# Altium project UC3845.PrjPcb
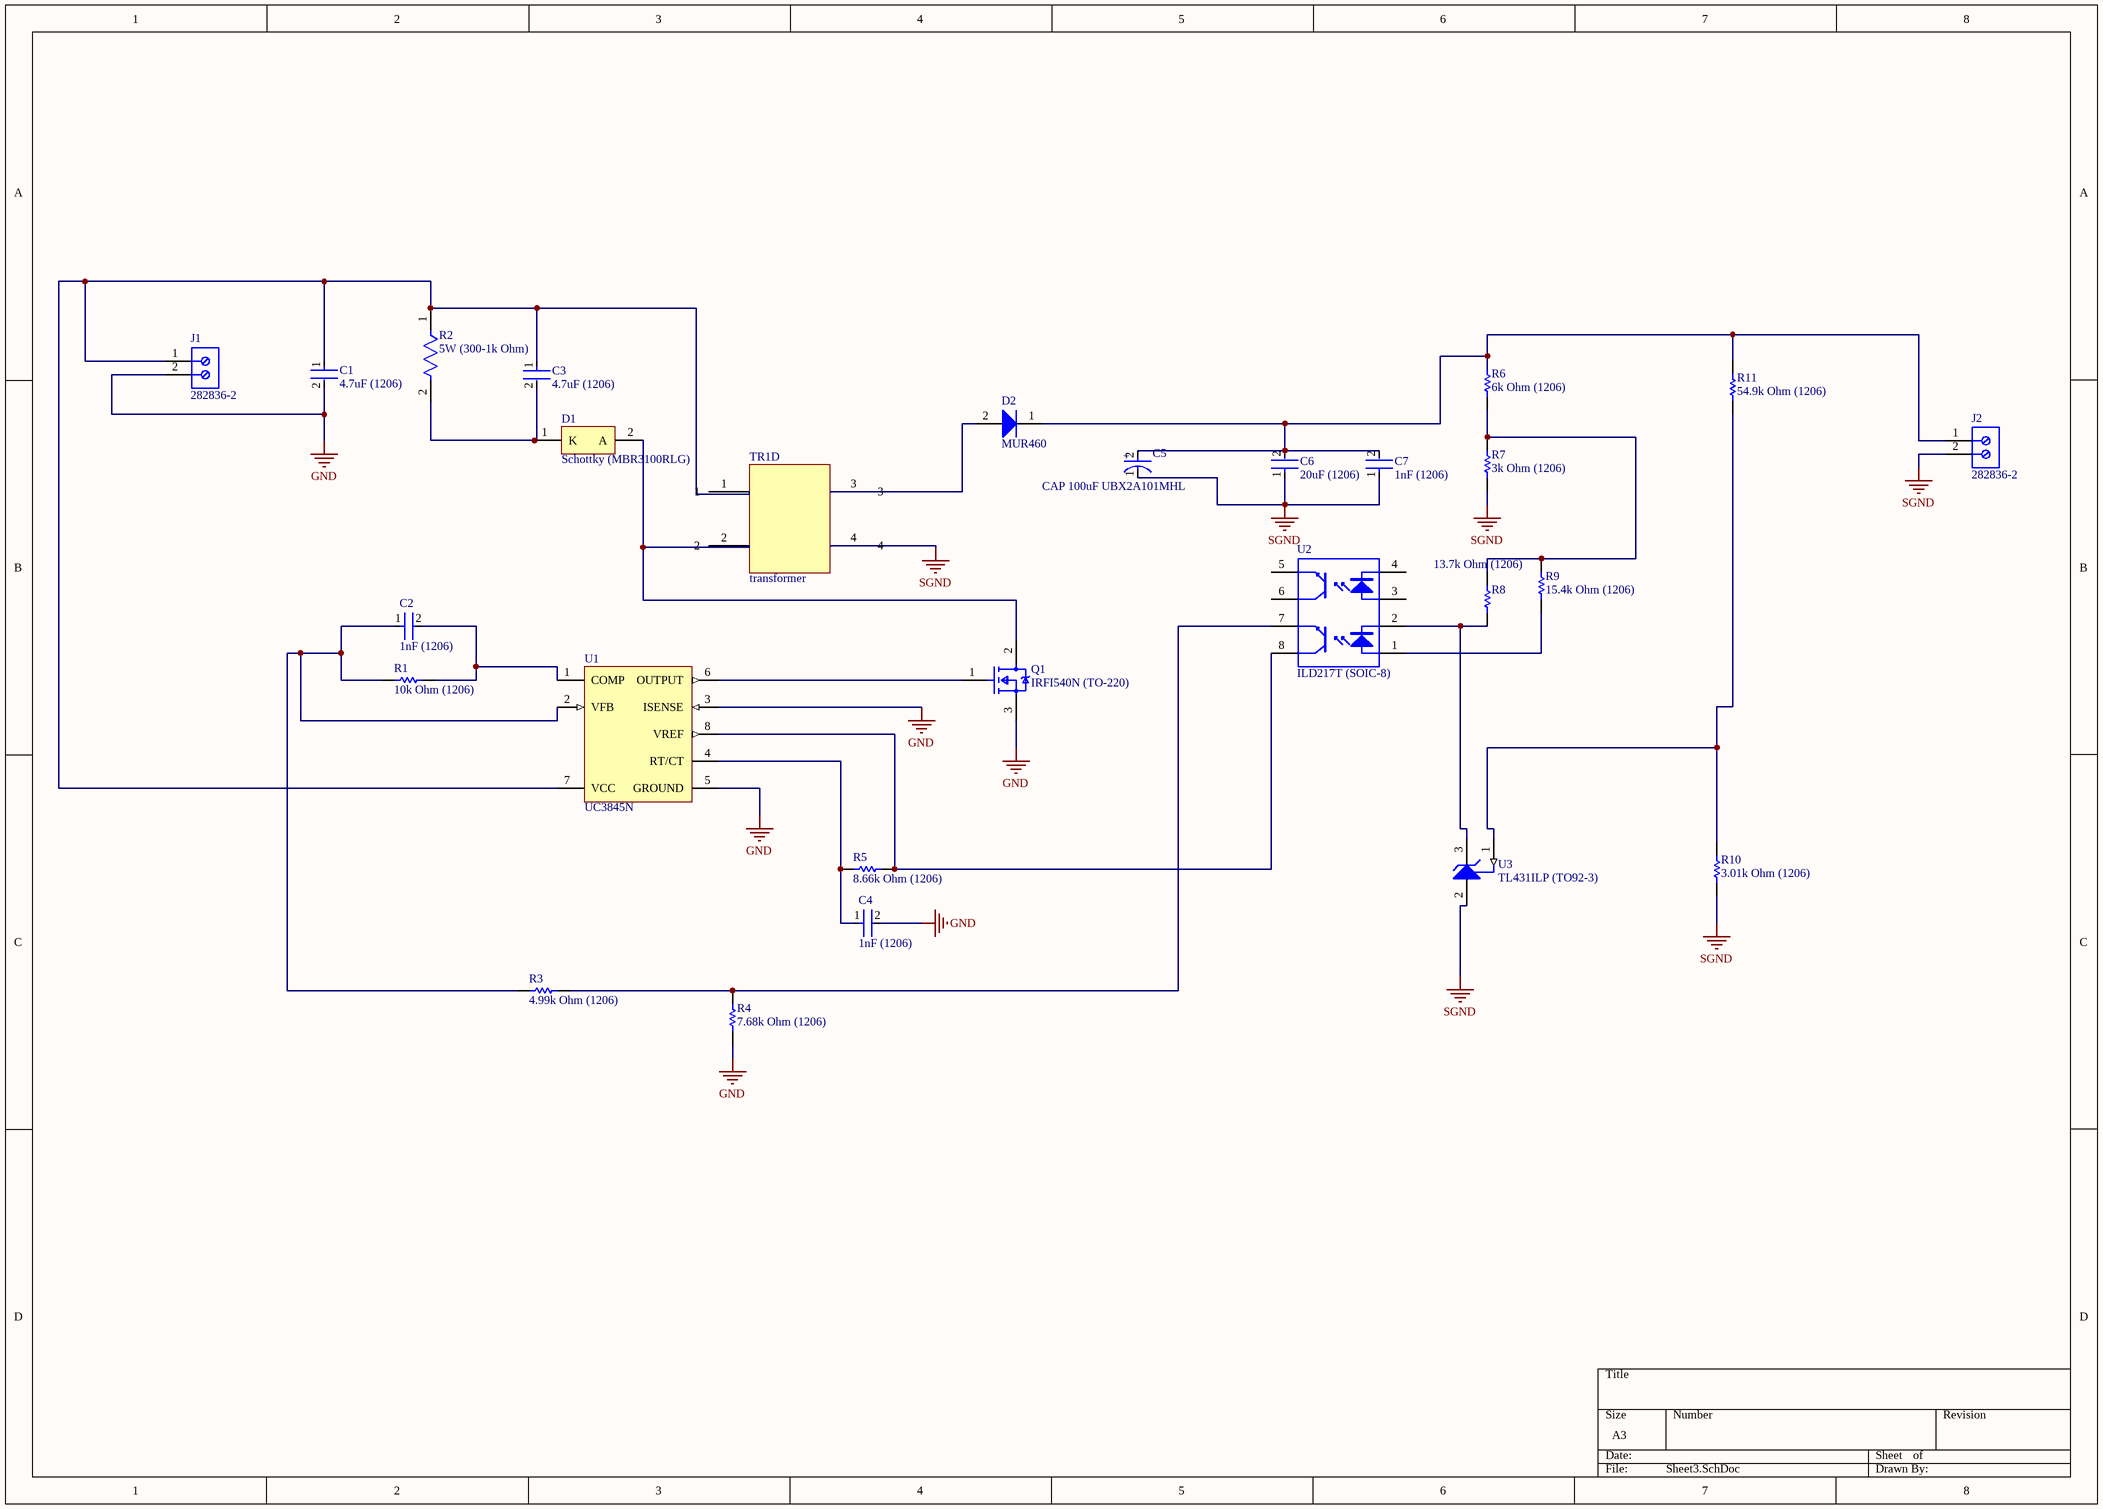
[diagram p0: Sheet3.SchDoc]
1 sheet, 27 parts. Net scope: global (net labels, ports and power ports of the same name join across sheets).
Board file: PCB2.PcbDoc

## Sheet Sheet3.SchDoc
size A3

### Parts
C1  4.7uF (1206)  [FP-C1206C-EB-MFG]
C2  1nF (1206)  [FP-C1206C-EB-MFG]
C3  4.7uF (1206)  [FP-C1206C-EB-MFG]
C4  1nF (1206)  [FP-C1206C-EB-MFG]
C5  CAP 100uF UBX2A101MHL  [FP-UBX2A101MHL-MFG]
C6  20uF (1206)  [FP-C1206C-EB-MFG]
C7  1nF (1206)  [FP-C1206C-EB-MFG]
D1  Schottky (MBR3100RLG)  [ONSC-AXIAL_LEAD-2-267-05_V]
D2  MUR460  [ONSC-AXIAL_LEAD-2-267-05_V]
J1  282836-2  [TECO-282836-2_V]
J2  282836-2  [TECO-282836-2_V]
Q1  IRFI540N (TO-220)  [FP-PG-TO220-3-MFG]
R1  10k Ohm (1206)  [RESC3216X60X45NL10T20]
R2  5W (300-1k Ohm)  [FP-SQP500-MFG]
R3  4.99k Ohm (1206)  [RESC3216X60X45NL10T20]
R4  7.68k Ohm (1206)  [RESC3216X60X45NL10T20]
R5  8.66k Ohm (1206)  [RESC3216X60X45NL10T20]
R6  6k Ohm (1206)  [RESC3216X60X45NL10T20]
R7  3k Ohm (1206)  [RESC3216X60X45NL10T20]
R8  13.7k Ohm (1206)  [RESC3216X60X45NL10T20]
R9  15.4k Ohm (1206)  [RESC3216X60X45NL10T20]
R10  3.01k Ohm (1206)  [RESC3216X60X45NL10T20]
R11  54.9k Ohm (1206)  [RESC3216X60X45NL10T20]
TR1  transformer  [Transformer_flyback]  (part D of 4)
U1  UC3845N  [P0008A]
U2  ILD217T (SOIC-8)  [VISH-SOIC-8_C_V]
U3  TL431ILP (TO92-3)  [LP0003A]

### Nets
GND: C1.2 C4.2 J1.2 Q1.3(S) R4.1 U1.3(ISENSE) U1.5(GROUND)
SGND: C5.1(C) C6.1 C7.1 J2.2 R7.2 R10.2 TR1.4 U3.2(ANODE)
NetC1_1: C1.1 C3.1 J1.1 R2.1 TR1.1 U1.7(VCC)
NetC2_1: C2.1 R1.2 R3.2 U1.2(VFB)
NetC2_2: C2.2 R1.1 U1.1(COMP)
NetC3_2: C3.2 D1.1(K) R2.2
NetC4_1: C4.1 R5.2 U1.4(RT/CT)
NetC5_2: C5.2(A) C6.2 C7.2 D2.1(K) J2.1 R6.1 R11.1
NetD1_2: D1.2(A) Q1.2(D) TR1.2
NetD2_2: D2.2(A) TR1.3
NetQ1_1: Q1.1(G) U1.6(OUTPUT)
NetR3_1: R3.1 R4.2 U2.7(E)
NetR5_1: R5.1 U1.8(VREF) U2.8(C)
NetR6_2: R6.2 R7.1 R8.1 R9.1
NetR8_2: R8.2 U2.2(K) U3.3(CATHODE)
NetR9_2: R9.2 U2.1(A)
NetR10_1: R10.1 R11.2 U3.1(REF)

Not connected (* = marked no-connect by the designer): U2 3(A) 4(K) 5(E) 6(C)

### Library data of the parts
C1-C4 C6 C7 = CMP-03020-000955-1: Multilayer Ceramic Capacitor, C Series, 1000 Pf, - 5%, C0g / Np0, 100 V, 1206 [3216 Metric] Rohs Compliant: Yes; Manufacturer: KEMET; Manufacturer Part Number: C1206C102J1GACTU; Capacitance: 1,000 pF; Voltage Rating: 100 V; Tolerance: 0.05; Automotive Grade: Grade 0; Temperature Coefficient: 15%; Value: 1,000 pF
C5 = CMP-12462-000004-1: CAP ALUM 100UF 20% 100V RADIAL; Manufacturer: Nichicon; Material: Aluminum; Automotive Grade: Grade 0; Ripple Current: 950mA; Leakage Current: 300uA; Life: 1000Hours; Dissipation Factor: 8%
D1 = CMP-1055-00020-1: Rectifier, 2-Pin Axial_Lead, Pb-Free, Tape and Reel; Manufacturer: On Semiconductor; Configuration: Single; IFSM Max (A): 150
D2 = CMP-0902-00067-1: SWITCHMODE(TM) Power Rectifier, 2-Pin Axial_Lead, Pb-Free, Bulk Bag; Manufacturer: On Semiconductor; IFSM Max (A): 110; Type: Ultrafast; VRRM Max (V): 600
J1 J2 = CMP-1684-00017-1: Female Header, Pitch 5 mm, 1 x 2 Position, Height 10 mm, Tail Length 3.5 mm, Rohs, Bulk; Manufacturer: TE Connectivity; Wire Gauge: 16-30AWG; Product Training Modules: Wire-to-BoardEurostyleTerminalBlocks; Clamp Material - Plating: Brass-NickelPlated; Voltage: 300V; Mating Orientation: HorizontalwithBoard; Current: 13.5A; Pitch: 0.197"(5.00mm); Screw Thread: M3; 3D Model: 282836-2.pdf; Other Names: 5ULV-02B / A98076; Dynamic Catalog: BuchananSeries; Number of Levels: 1; Torque - Screw: 0.68Nm(6Lb-In); Featured Product: EurostyleTerminalBlockConnectors; Positions Per Level: 2; Wire Termination: Screw-RisingCageClamp
Q1 = CMP-32901-000575-1: MOSFET N-CH 100V 20A TO220FP; Gate to Source Voltage (Vgs): 20V; Power Dissipation: 54W; Rds On Max: 52mR; Threshold Voltage: 4V; Turn-On Delay Time: 8.2ns; Turn-Off Delay Time: 44ns; Input Capacitance: 1.4nF; Element Configuration: Single
R1 R3-R11 = CMP-2003-02424-1: Manufacturer: Vishay Dale; Part Number: CRCW12068R25FKEA
R2 = CMP-03413-000003-1: Manufacturer Part Number: SQP500JB-1R2; Manufacturer: Yageo; Temperature Coefficient: 300ppm/°C; Resistance: 1.2Ω; Tolerance: 5%; Value: 1.2Ω; Voltage Rating: 350V
U1 = CMP-0319-00305-2: PWM Controller with Current Control, 50 % Duty Cycle, 0 to +70 degC, 8-pin PDIP (P), Green (RoHS & no Sb/Br); Manufacturer: Texas Instruments; Rating: Catalog; UVLO Thresholds On/Off(V): 8.4/7.6; Regulated Outputs(#): 1; Duty Cycle(Max)(%): 50; Frequency(Max)(kHz): 450; Topology: Boost, Buck, Flyback, Forward
U2 = CMP-2000-06453-1: Optocoupler, Phototransistor Output, Dual Channel, 4000 VRMS, -55 to 100 degC, 8-Pin SOIC, RoHS, Tape and Reel; Manufacturer: Vishay; Voltage - Output (Max): 70V; Vce Saturation (Max): 400mV; Number of Channels: 2; Voltage - Forward (Vf) (Typ): 1.2V; EDA / CAD Models: DownloadfromAcceleratedDesigns; Current Transfer Ratio (Min): 100%@10mA; Current Transfer Ratio (Max): 200%@10mA; Input Type: DC; Current - DC Forward (If) (Max): 30mA; Rise / Fall Time (Typ): 3µs,4.7µs; Turn On / Turn Off Time (Typ): 6µs,5µs; Catalog Drawings: OptocouplerCircuit; Other Names: 751-1310-1ILD207TGICTILD207TGICT-ND; Online Catalog: ILD205T,206T,207T,211T,213T,217TSeries
U3 = CMP-0366-00043-2: Adjustable Precision Shunt Regulator, 34 ppm / degC, 100 mA, -40 to 85 degC, 3-pin TO-92 (LP), Pb-Free (RoHS); Manufacturer: Texas Instruments; Iout/Iz(Max)(mA): 100; Rating: Military; Temp Coeff(Typ)(ppm/ degree C): 34; Initial Accuracy @ 25/deg C(%): 2; SubFamily: Shunt Voltage Reference; VO Adj(Max)(V): 36; VO Adj(Min)(V): 2.495; Temp Coeff(Max)(ppm/ degree C): 92; Min Iz for Regulation(uA): 600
